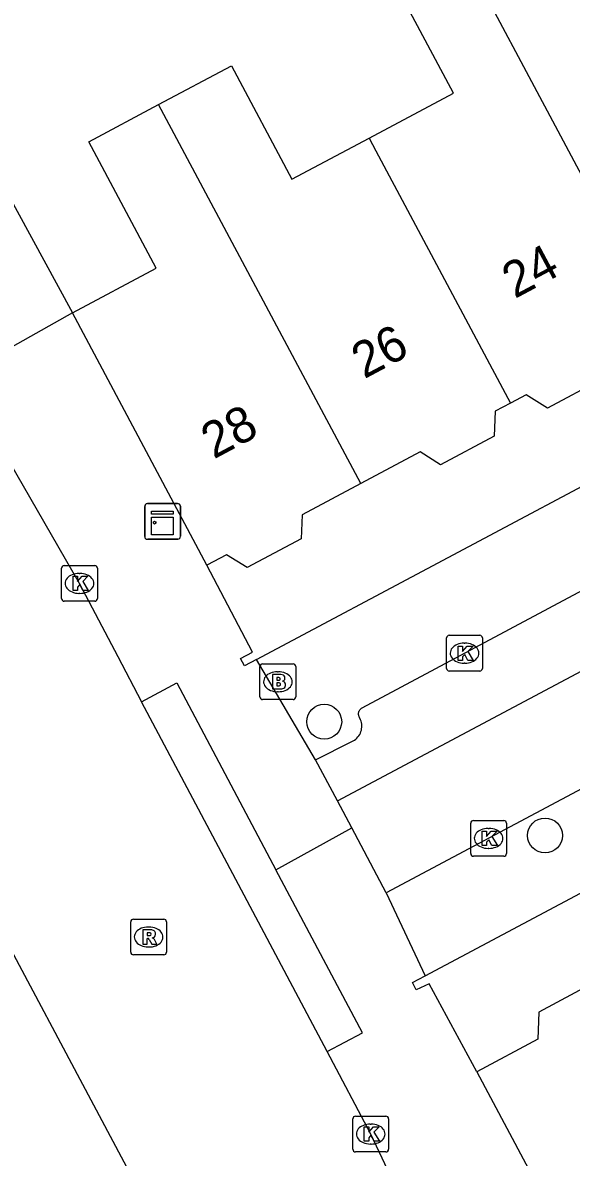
# Model space of a CAD drawing. Extents: x 160304 to 160954, y 383686 to 384161.
# Drawn here: x 160672.12 to 160687.46, y 383907.81 to 383939.55 of the extents above; entities that cross this region are included whole.
import ezdxf

# ---------------------------------------------------------------- set-up
doc = ezdxf.new("R2010")
doc.units = 0
for name, color, linetype in [('IMGEO_Boom', 7, 'Continuous'), ('IMGEO_Brandkraan', 7, 'Continuous'), ('IMGEO_Kast', 7, 'Continuous'), ('IMGEO_Kolk', 7, 'Continuous'), ('IMGEO_Pand', 7, 'Continuous'), ('IMGEO_Pand_nummerreeks', 7, 'Continuous'), ('IMGEO_Rijbaan_lokaal_open', 7, 'Continuous'), ('IMGEO_Rioolput', 7, 'Continuous'), ('IMGEO_Voetpad_open', 7, 'Continuous')]:
    doc.layers.add(name, color=color, linetype=linetype)

msp = doc.modelspace()

# ---------------------------------------------------------------- linework, layer by layer
at = {"layer": 'IMGEO_Boom'}
for centre in [(160680.55, 383919.999), (160686.729, 383916.816)]:
    msp.add_circle(centre, 0.489, dxfattribs=at)
at = {"layer": 'IMGEO_Brandkraan'}
for p, q in [((160678.754, 383920.691), (160678.754, 383921.543)), ((160678.829, 383921.617), (160679.681, 383921.617)), ((160679.755, 383921.543), (160679.755, 383920.691)), ((160679.242, 383921.397), (160679.267, 383921.397)), ((160679.681, 383920.617), (160678.829, 383920.617)), ((160679.265, 383920.837), (160679.24, 383920.837))]:
    msp.add_line(p, q, dxfattribs=at)
for points in [[(160678.754, 383920.691), (160678.754, 383921.543)], [(160678.829, 383921.617), (160679.681, 383921.617)], [(160679.755, 383921.543), (160679.755, 383920.691)], [(160679.102, 383921.317), (160679.102, 383920.917), (160679.315, 383920.917)], [(160679.333, 383921.317), (160679.102, 383921.317)], [(160679.281, 383921.236), (160679.227, 383921.236), (160679.227, 383921.16)], [(160679.227, 383921.16), (160679.28, 383921.16)], [(160679.289, 383921.084), (160679.227, 383921.084), (160679.227, 383921.003)], [(160679.227, 383921.003), (160679.289, 383921.003)], [(160679.681, 383920.617), (160678.829, 383920.617)]]:
    msp.add_lwpolyline(points, dxfattribs=at)
for centre, radius, start, end in [((160678.831, 383921.541), 0.0765, 91.552, 178.448), ((160678.831, 383921.541), 0.0765, 91.552, 178.448), ((160679.679, 383921.541), 0.0765, 1.552, 88.448), ((160679.679, 383921.541), 0.0765, 1.552, 88.448), ((160679.282, 383921.198), 0.0379, 267.8285, 90.9355), ((160679.337, 383921.172), 0.145, 59.4692, 91.5367), ((160679.362, 383921.219), 0.0922, 285.5137, 58.1501), ((160679.29, 383921.043), 0.0404, 269.8759, 90.5077), ((160679.321, 383921.168), 0.251, 268.6676, 293.5347), ((160679.367, 383921.027), 0.105, 301.3115, 78.989), ((160678.831, 383920.693), 0.0765, 181.552, 268.448), ((160678.831, 383920.693), 0.0765, 181.552, 268.448), ((160679.679, 383920.693), 0.0765, 271.552, 358.448), ((160679.679, 383920.693), 0.0765, 271.552, 358.448)]:
    msp.add_arc(centre, radius, start, end, dxfattribs=at)
for centre, major_axis, ratio, start_param, end_param in [((160679.241, 383921.117), (-0.387, 0.002), 0.722429, 4.712389, 7.853982), ((160679.266, 383921.117), (-0.39, 0.002), 0.717154, 1.570796, 4.712389)]:
    msp.add_ellipse(centre, major_axis=major_axis, ratio=ratio, start_param=start_param, end_param=end_param, dxfattribs=at)
at = {"layer": 'IMGEO_Kast'}
for p, q in [((160675.529, 383925.178), (160675.529, 383926.019)), ((160675.529, 383926.019), (160675.529, 383925.178)), ((160675.604, 383926.103), (160676.445, 383926.103)), ((160676.445, 383926.103), (160675.604, 383926.103)), ((160676.529, 383926.028), (160676.529, 383925.187)), ((160676.529, 383925.187), (160676.529, 383926.028)), ((160676.454, 383925.103), (160675.613, 383925.103)), ((160675.613, 383925.103), (160676.454, 383925.103))]:
    msp.add_line(p, q, dxfattribs=at)
for points in [[(160675.724, 383925.893), (160676.324, 383925.893), (160676.324, 383925.808), (160675.724, 383925.808), (160675.724, 383925.893)], [(160675.724, 383925.718), (160676.324, 383925.718), (160676.324, 383925.229), (160675.724, 383925.229), (160675.724, 383925.718)]]:
    msp.add_lwpolyline(points, dxfattribs=at)
msp.add_circle((160675.808, 383925.567), 0.0377, dxfattribs=at)
for centre, start, end in [((160675.607, 383926.025), 92.4484, 184.2845), ((160675.607, 383926.025), 92.4484, 184.2845), ((160676.451, 383926.025), 2.4484, 94.2845), ((160676.451, 383926.025), 2.4484, 94.2845), ((160675.607, 383925.181), 182.4484, 274.2845), ((160675.607, 383925.181), 182.4484, 274.2845), ((160676.451, 383925.181), 272.4484, 4.2845), ((160676.451, 383925.181), 272.4484, 4.2845)]:
    msp.add_arc(centre, 0.0779, start, end, dxfattribs=at)
at = {"layer": 'IMGEO_Kolk'}
for p, q in [((160673.28, 383924.369), (160674.132, 383924.369)), ((160673.205, 383923.443), (160673.205, 383924.295)), ((160673.693, 383924.149), (160673.718, 383924.149)), ((160674.206, 383924.295), (160674.206, 383923.443)), ((160673.716, 383923.589), (160673.691, 383923.589)), ((160674.132, 383923.369), (160673.28, 383923.369)), ((160683.975, 383921.49), (160683.975, 383922.342)), ((160684.05, 383922.416), (160684.902, 383922.416)), ((160684.463, 383922.196), (160684.488, 383922.196)), ((160684.976, 383922.342), (160684.976, 383921.49)), ((160684.486, 383921.636), (160684.461, 383921.636)), ((160684.902, 383921.416), (160684.05, 383921.416)), ((160684.648, 383916.309), (160684.648, 383917.161)), ((160684.723, 383917.235), (160685.575, 383917.235)), ((160685.649, 383917.161), (160685.649, 383916.309)), ((160685.136, 383917.015), (160685.161, 383917.015)), ((160685.159, 383916.455), (160685.134, 383916.455)), ((160685.575, 383916.235), (160684.723, 383916.235)), ((160681.351, 383908.038), (160681.351, 383908.89)), ((160681.426, 383908.964), (160682.278, 383908.964)), ((160682.352, 383908.89), (160682.352, 383908.038)), ((160681.839, 383908.744), (160681.864, 383908.744)), ((160681.862, 383908.184), (160681.837, 383908.184)), ((160682.278, 383907.964), (160681.426, 383907.964))]:
    msp.add_line(p, q, dxfattribs=at)
for points in [[(160673.28, 383924.369), (160674.132, 383924.369)], [(160673.205, 383923.443), (160673.205, 383924.295)], [(160673.526, 383924.069), (160673.649, 383924.069), (160673.649, 383923.918), (160673.779, 383924.069), (160673.943, 383924.069), (160673.797, 383923.918), (160673.95, 383923.669), (160673.798, 383923.669), (160673.713, 383923.833), (160673.649, 383923.766), (160673.649, 383923.669), (160673.526, 383923.669), (160673.526, 383924.069)], [(160674.206, 383924.295), (160674.206, 383923.443)], [(160674.132, 383923.369), (160673.28, 383923.369)], [(160683.975, 383921.49), (160683.975, 383922.342)], [(160684.05, 383922.416), (160684.902, 383922.416)], [(160684.976, 383922.342), (160684.976, 383921.49)], [(160684.296, 383922.116), (160684.419, 383922.116), (160684.419, 383921.965), (160684.549, 383922.116), (160684.713, 383922.116), (160684.567, 383921.965), (160684.72, 383921.716), (160684.568, 383921.716), (160684.483, 383921.88), (160684.419, 383921.813), (160684.419, 383921.716), (160684.296, 383921.716), (160684.296, 383922.116)], [(160684.902, 383921.416), (160684.05, 383921.416)], [(160684.648, 383916.309), (160684.648, 383917.161)], [(160684.723, 383917.235), (160685.575, 383917.235)], [(160685.649, 383917.161), (160685.649, 383916.309)], [(160684.969, 383916.935), (160685.092, 383916.935), (160685.092, 383916.784), (160685.222, 383916.935), (160685.386, 383916.935), (160685.24, 383916.784), (160685.393, 383916.535), (160685.241, 383916.535), (160685.156, 383916.699), (160685.092, 383916.632), (160685.092, 383916.535), (160684.969, 383916.535), (160684.969, 383916.935)], [(160685.575, 383916.235), (160684.723, 383916.235)], [(160681.351, 383908.038), (160681.351, 383908.89)], [(160681.426, 383908.964), (160682.278, 383908.964)], [(160682.352, 383908.89), (160682.352, 383908.038)], [(160681.672, 383908.664), (160681.795, 383908.664), (160681.795, 383908.513), (160681.925, 383908.664), (160682.089, 383908.664), (160681.943, 383908.513), (160682.096, 383908.264), (160681.944, 383908.264), (160681.859, 383908.428), (160681.795, 383908.361), (160681.795, 383908.264), (160681.672, 383908.264), (160681.672, 383908.664)], [(160682.278, 383907.964), (160681.426, 383907.964)]]:
    msp.add_lwpolyline(points, dxfattribs=at)
for centre, start, end in [((160673.282, 383924.293), 91.552, 178.448), ((160673.282, 383924.293), 91.552, 178.448), ((160674.13, 383924.293), 1.552, 88.448), ((160674.13, 383924.293), 1.552, 88.448), ((160673.282, 383923.445), 181.552, 268.448), ((160673.282, 383923.445), 181.552, 268.448), ((160674.13, 383923.445), 271.552, 358.448), ((160674.13, 383923.445), 271.552, 358.448), ((160684.052, 383922.34), 91.552, 178.448), ((160684.052, 383922.34), 91.552, 178.448), ((160684.9, 383922.34), 1.552, 88.448), ((160684.9, 383922.34), 1.552, 88.448), ((160684.052, 383921.492), 181.552, 268.448), ((160684.052, 383921.492), 181.552, 268.448), ((160684.9, 383921.492), 271.552, 358.448), ((160684.9, 383921.492), 271.552, 358.448), ((160684.725, 383917.159), 91.552, 178.448), ((160684.725, 383917.159), 91.552, 178.448), ((160685.573, 383917.159), 1.552, 88.448), ((160685.573, 383917.159), 1.552, 88.448), ((160684.725, 383916.311), 181.552, 268.448), ((160684.725, 383916.311), 181.552, 268.448), ((160685.573, 383916.311), 271.552, 358.448), ((160685.573, 383916.311), 271.552, 358.448), ((160681.428, 383908.888), 91.552, 178.448), ((160681.428, 383908.888), 91.552, 178.448), ((160682.276, 383908.888), 1.552, 88.448), ((160682.276, 383908.888), 1.552, 88.448), ((160681.428, 383908.04), 181.552, 268.448), ((160681.428, 383908.04), 181.552, 268.448), ((160682.276, 383908.04), 271.552, 358.448), ((160682.276, 383908.04), 271.552, 358.448)]:
    msp.add_arc(centre, 0.0765, start, end, dxfattribs=at)
for centre, major_axis, ratio, start_param, end_param in [((160673.692, 383923.869), (-0.387, 0.002), 0.722429, 4.712389, 7.853982), ((160673.717, 383923.869), (-0.39, 0.002), 0.717154, 1.570796, 4.712389), ((160684.462, 383921.916), (-0.387, 0.002), 0.722429, 4.712389, 7.853982), ((160684.487, 383921.916), (-0.39, 0.002), 0.717154, 1.570796, 4.712389), ((160685.135, 383916.735), (-0.387, 0.002), 0.722429, 4.712389, 7.853982), ((160685.16, 383916.735), (-0.39, 0.002), 0.717154, 1.570796, 4.712389), ((160681.838, 383908.464), (-0.387, 0.002), 0.722429, 4.712389, 7.853982), ((160681.863, 383908.464), (-0.39, 0.002), 0.717154, 1.570796, 4.712389)]:
    msp.add_ellipse(centre, major_axis=major_axis, ratio=ratio, start_param=start_param, end_param=end_param, dxfattribs=at)
at = {"layer": 'IMGEO_Pand'}
for points in [[(160681.808, 383936.323), (160684.167, 383937.579), (160682.515, 383940.683), (160684.35, 383941.66)], [(160684.35, 383941.66), (160689.965, 383931.129)], [(160675.917, 383937.262), (160677.959, 383938.349), (160679.649, 383935.174), (160681.808, 383936.323)], [(160673.507, 383931.437), (160675.848, 383932.683), (160673.964, 383936.223), (160675.917, 383937.262)], [(160681.571, 383926.662), (160675.917, 383937.262)], [(160681.808, 383936.323), (160681.998, 383935.966), (160685.76, 383928.912)], [(160677.267, 383924.375), (160673.507, 383931.437)], [(160689.965, 383931.129), (160688.324, 383930.255), (160688.301, 383929.573), (160686.799, 383928.773), (160686.2, 383929.147), (160685.76, 383928.912)], [(160685.76, 383928.912), (160685.329, 383928.683), (160685.306, 383927.99), (160683.802, 383927.189), (160683.231, 383927.546), (160681.571, 383926.662)], [(160681.571, 383926.662), (160679.93, 383925.788), (160679.907, 383925.117), (160678.392, 383924.311), (160677.819, 383924.669), (160677.267, 383924.375)], [(160689.243, 383912.618), (160688.66, 383912.307), (160688.063, 383912.68), (160686.554, 383911.876), (160686.528, 383911.116), (160684.818, 383910.205)], [(160684.818, 383910.205), (160690.46, 383899.614)]]:
    msp.add_lwpolyline(points, dxfattribs=at)
at = {"layer": 'IMGEO_Rijbaan_lokaal_open'}
for points in [[(160680.921, 383917.781), (160721.467, 383939.366)], [(160722.832, 383936.801), (160682.288, 383915.213)], [(160671.738, 383927.276), (160673.701, 383923.877), (160674.779, 383921.821), (160675.442, 383920.557)], [(160680.633, 383910.769), (160675.442, 383920.557)], [(160681.322, 383917.027), (160680.921, 383917.781)], [(160669.847, 383917.258), (160675.723, 383906.234)], [(160682.288, 383915.213), (160681.322, 383917.027)], [(160687.649, 383895.859), (160687.584, 383895.992), (160683.512, 383904.948), (160681.85, 383908.464), (160680.633, 383910.769)]]:
    msp.add_lwpolyline(points, dxfattribs=at)
at = {"layer": 'IMGEO_Rioolput'}
for p, q in [((160675.139, 383913.55), (160675.139, 383914.402)), ((160675.214, 383914.476), (160676.066, 383914.476)), ((160675.627, 383914.256), (160675.652, 383914.256)), ((160676.14, 383914.402), (160676.14, 383913.55)), ((160675.65, 383913.696), (160675.625, 383913.696)), ((160676.066, 383913.476), (160675.214, 383913.476))]:
    msp.add_line(p, q, dxfattribs=at)
for points in [[(160675.139, 383913.55), (160675.139, 383914.402)], [(160675.214, 383914.476), (160676.066, 383914.476)], [(160676.14, 383914.402), (160676.14, 383913.55)], [(160675.728, 383914.174), (160675.476, 383914.176), (160675.476, 383913.776)], [(160675.476, 383913.776), (160675.6, 383913.776), (160675.6, 383913.938), (160675.611, 383913.938)], [(160675.654, 383914.095), (160675.6, 383914.095), (160675.6, 383914.014)], [(160675.6, 383914.014), (160675.652, 383914.014)], [(160675.658, 383913.909), (160675.729, 383913.776), (160675.869, 383913.776), (160675.804, 383913.902)], [(160676.066, 383913.476), (160675.214, 383913.476)]]:
    msp.add_lwpolyline(points, dxfattribs=at)
for centre, radius, start, end in [((160675.216, 383914.4), 0.0765, 91.552, 178.448), ((160675.216, 383914.4), 0.0765, 91.552, 178.448), ((160676.064, 383914.4), 0.0765, 1.552, 88.448), ((160676.064, 383914.4), 0.0765, 1.552, 88.448), ((160675.61, 383913.885), 0.0533, 26.0293, 88.6989), ((160675.636, 383914.203), 0.19, 274.7715, 282.9687), ((160675.66, 383913.999), 0.0964, 77.0061, 93.1865), ((160675.674, 383914.056), 0.0378, 276.6634, 79.6772), ((160675.727, 383914.064), 0.109, 350.3612, 89.416), ((160675.725, 383914.064), 0.112, 277.5842, 350.9817), ((160675.709, 383913.849), 0.108, 29.5134, 73.7905), ((160675.216, 383913.552), 0.0765, 181.552, 268.448), ((160675.216, 383913.552), 0.0765, 181.552, 268.448), ((160676.064, 383913.552), 0.0765, 271.552, 358.448), ((160676.064, 383913.552), 0.0765, 271.552, 358.448)]:
    msp.add_arc(centre, radius, start, end, dxfattribs=at)
for centre, major_axis, ratio, start_param, end_param in [((160675.626, 383913.976), (-0.387, 0.002), 0.722429, 4.712389, 7.853982), ((160675.651, 383913.976), (-0.39, 0.002), 0.717154, 1.570796, 4.712389)]:
    msp.add_ellipse(centre, major_axis=major_axis, ratio=ratio, start_param=start_param, end_param=end_param, dxfattribs=at)
at = {"layer": 'IMGEO_Voetpad_open'}
for points in [[(160678.654, 383921.738), (160737.631, 383953.138)], [(160666.961, 383943.459), (160673.507, 383931.437)], [(160683.374, 383912.887), (160731.321, 383938.411)], [(160673.507, 383931.437), (160670.424, 383929.702)], [(160680.31, 383918.928), (160681.327, 383919.444), (160681.365, 383919.464), (160681.401, 383919.487), (160681.435, 383919.513), (160681.466, 383919.542), (160681.495, 383919.573), (160681.52, 383919.607), (160681.543, 383919.644), (160681.562, 383919.682), (160681.578, 383919.721), (160681.59, 383919.762), (160681.598, 383919.804), (160681.603, 383919.847), (160681.603, 383919.889), (160681.6, 383919.932), (160681.594, 383919.974), (160681.583, 383920.015), (160681.569, 383920.055), (160681.551, 383920.094), (160681.537, 383920.12), (160681.532, 383920.129), (160681.525, 383920.144), (160681.519, 383920.161), (160681.515, 383920.178), (160681.513, 383920.195), (160681.511, 383920.212), (160681.512, 383920.229), (160681.514, 383920.247), (160681.517, 383920.264), (160681.522, 383920.28), (160681.529, 383920.296), (160681.536, 383920.312), (160681.546, 383920.327), (160681.556, 383920.341), (160681.568, 383920.353), (160681.581, 383920.365), (160681.594, 383920.376), (160681.609, 383920.385), (160696.18, 383928.165)], [(160678.654, 383921.738), (160678.321, 383921.561), (160678.205, 383921.771), (160678.544, 383921.946), (160677.267, 383924.375)], [(160680.31, 383918.928), (160678.654, 383921.738)], [(160675.442, 383920.557), (160676.432, 383921.082), (160679.202, 383915.859)], [(160680.921, 383917.781), (160680.31, 383918.928)], [(160679.202, 383915.859), (160681.322, 383917.027)], [(160680.633, 383910.769), (160681.624, 383911.294), (160679.202, 383915.859)], [(160682.288, 383915.213), (160683.374, 383912.887)], [(160684.818, 383910.205), (160683.49, 383912.67), (160683.119, 383912.501), (160683.022, 383912.699), (160683.374, 383912.887)]]:
    msp.add_lwpolyline(points, dxfattribs=at)

# ---------------------------------------------------------------- texts
at = {"layer": 'IMGEO_Pand_nummerreeks'}
for s, p in [('24', (160685.879, 383931.821)), ('26', (160681.668, 383929.577)), ('28', (160677.46, 383927.333))]:
    msp.add_text(s, height=1, rotation=28.0578, dxfattribs=at).set_placement(p)

doc.saveas('drawing.dxf')
